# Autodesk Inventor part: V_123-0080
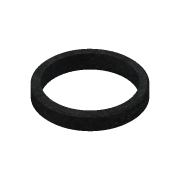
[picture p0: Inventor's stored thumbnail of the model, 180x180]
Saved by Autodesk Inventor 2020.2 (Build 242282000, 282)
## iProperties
Created: 2006-02
Part Number: V_123-0080
Document SubType Name: Modeling
Designer: F.Stasiak
Description: Tuleja dystansowa 25x30x5
Material: St 5
Project: Przekładnia X51
Density: 7.85 g/cm^3
Appearance: Stal metaliczna (platerowana)
Manager: www.cadconsulting.pl
Company: Fabian Stasiak CAD Consulting
Author: F.Stasiak
Subject: Zbiór ćwiczeń. Autodesk Inventor 2020. Kurs podstawowy
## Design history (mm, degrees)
sketch "Szkic1"
  geometry: C1 r 12.5 at (0, 0); C2 r 15 at (0, 0); 1 further point
  constraints: 2 centre point, 2 coincident
  dimensions: "d0" = 25 diameter of C1; "d1" = 30 diameter of C2
extrude "Wyciągnięcie proste1" new body sketch "Szkic1" distance "d2" = 5; taper "d3" = 0 deg
chamfer "Faza1" distance "d4" = 0.5; stored, may be unused: second distance "d5" = 2, angle "d6" = 45 deg
node "Bryła1"
node "Korpusy bryłowe"
node "Korpusy powierzchniowe"
